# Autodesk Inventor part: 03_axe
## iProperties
Shininess: 31.0
Length Units: 11269
Angle Units: 11279
Time Units: 11290
Mass Units: 11283
Length Display Precision: 3
Angle Display Precision: 2
Compacted: True
Created: 2002-11
Part Number: 03_axe
Material: Acier doux
Document SubType Name: Modélisation
Designer: poste-2
MajorVersion: 11
MinorVersion: 1
Density: 7.86
Volumn: 1.677510786885382
Area: 10.323396518310158
PropertySet Name: Model Information
Control State: 0
Master: False
Checked Out: False
Author: poste-2
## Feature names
1. Révolution1 [Revolution]
2. Extrusion1
3. Extrusion2
